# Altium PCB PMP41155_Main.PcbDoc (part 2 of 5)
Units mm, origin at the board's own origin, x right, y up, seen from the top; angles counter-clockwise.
Board outline 74 x 146.5 mm, 8 copper layers (Top Layer, Signal Layer 1, Signal Layer 2, Signal Layer 3, Signal Layer 4, Signal Layer 5, Signal Layer 6, Bottom Layer), stack 1.534 mm thick; 249 components, 190 nets, 902 pads, 747 vias.
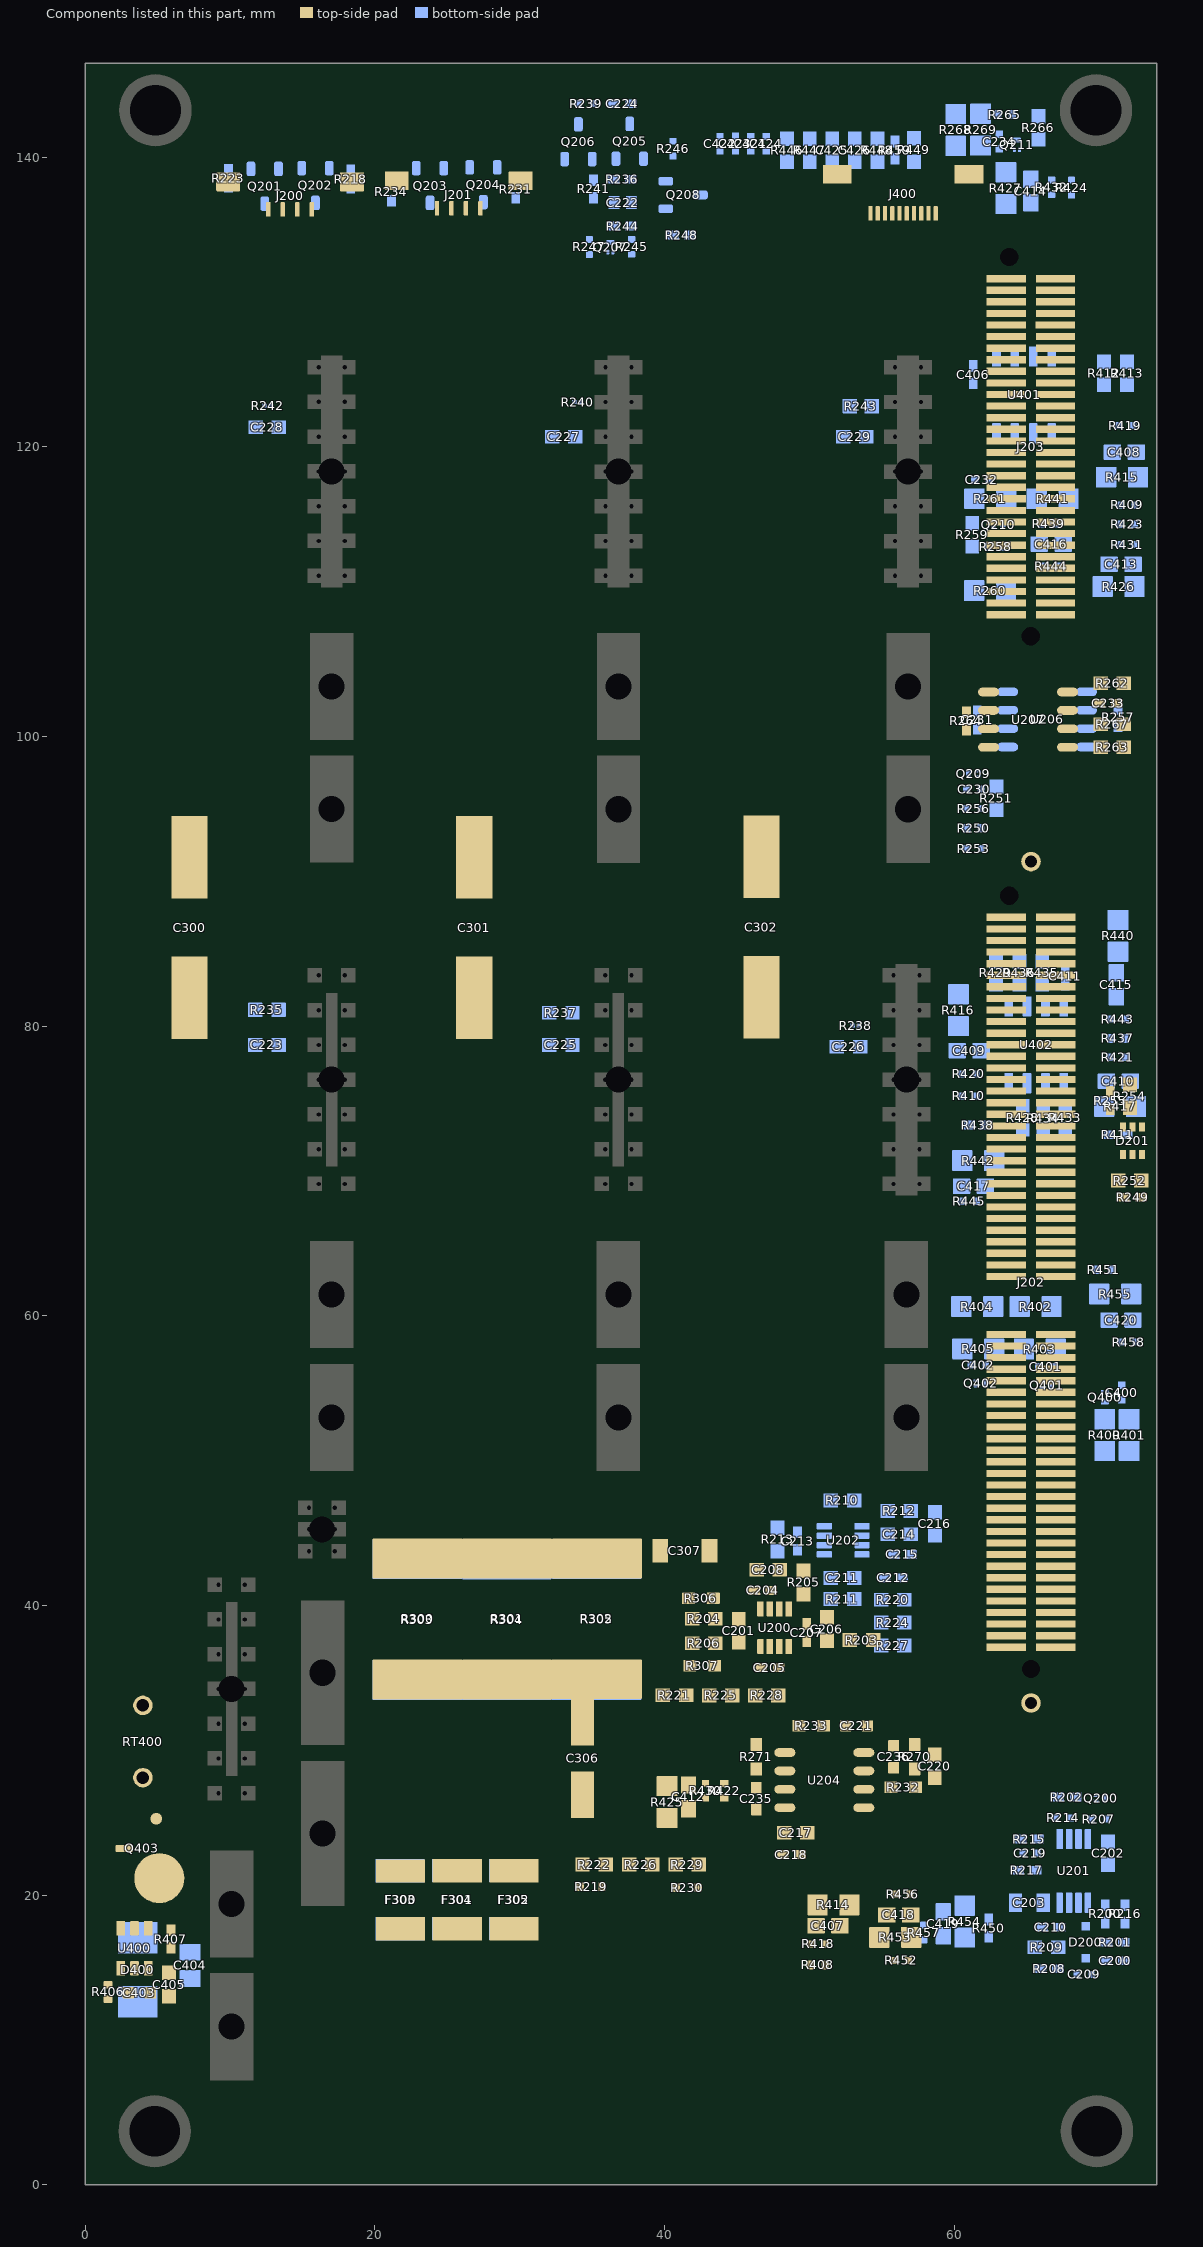
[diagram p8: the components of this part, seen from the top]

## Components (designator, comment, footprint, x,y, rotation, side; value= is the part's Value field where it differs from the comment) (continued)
C230 "885012205001" WCAP-CSGP_0402_L1W0.5H0.5 61.38,96.38 r180 bottom
C231 "CMP-0006623-2" 0402 61.59,101.155 r270 bottom value=0.1uF
C232 "885012205001" WCAP-CSGP_0402_L1W0.5H0.5 61.92,117.74 r0 bottom
C233 "CMP-0006623-2" 0402 70.63,102.3 r0 top value=0.1uF
C234 "885012205001" WCAP-CSGP_0402_L1W0.5H0.5 63.121,141.09 r90 bottom
C235 "06035C100KAT2A" FP-06035C100KAT2A_0603-MFG 46.34,26.664 r90 top value=10pF
C236 "06035C100KAT2A" FP-06035C100KAT2A_0603-MFG 55.825,29.559 r270 top value=10pF
C300 "EMVY630ATR101MKE0S" CAPSMT_62_KE0 7.21,86.81 r90 top value=100uF
C301 "EMVY630ATR101MKE0S" CAPSMT_62_KE0 26.86,86.81 r90 top value=100uF
C302 "EMVY630ATR101MKE0S" CAPSMT_62_KE0 46.7,86.84 r90 top value=100uF
C306 "63PFV22M6.3X8" SM_RADIAL_D 34.35,29.44 r270 top value=22uF
C307 "GRJ31CC72A475KE01L" 1206_180 41.41,43.78 r0 top value=4.7uF
C400 "885012205001" WCAP-CSGP_0402_L1W0.5H0.5 71.574,54.705 r270 bottom
C401 "885012205001" WCAP-CSGP_0402_L1W0.5H0.5 66.33,56.505 r0 bottom
C402 "885012205001" WCAP-CSGP_0402_L1W0.5H0.5 61.67,56.609 r0 bottom
C403 "885012206120" FP-885012206120_0603-MFG 3.74,13.26 r180 top value=100nF
C404 "KAF21KR72A105KU" 0805_150 7.24,15.15 r270 bottom value=1uF
C405 "GRM188R71E104KA01D" 0603 5.796,13.831 r270 top value=0.1uF
C406 "CMP-0006623-2" 0402 61.328,124.99 r270 bottom value=0.1uF
C407 "C0603C153K5RACTU" FP-C0603C153K5RACTU_0603-IPC_A 51.291,17.886 r0 top
C408 "C0603C153K5RACTU" FP-C0603C153K5RACTU_0603-IPC_A 71.75,119.64 r180 bottom
C409 "C0603C153K5RACTU" FP-C0603C153K5RACTU_0603-IPC_A 61.04,78.31 r0 bottom
C410 "C0603C153K5RACTU" FP-C0603C153K5RACTU_0603-IPC_A 71.341,76.208 r0 bottom
C411 "CMP-0006623-2" 0402 67.681,83.465 r270 bottom value=0.1uF
C412 "C0603C153K5RACTU" FP-C0603C153K5RACTU_0603-IPC_A 41.658,26.782 r270 top
C413 "C0603C153K5RACTU" FP-C0603C153K5RACTU_0603-IPC_A 71.53,111.897 r180 bottom
C414 "C0603C153K5RACTU" FP-C0603C153K5RACTU_0603-IPC_A 65.3,137.674 r90 bottom
C415 "C0603C153K5RACTU" FP-C0603C153K5RACTU_0603-IPC_A 71.205,82.865 r270 bottom
C416 "C0603C153K5RACTU" FP-C0603C153K5RACTU_0603-IPC_A 66.71,113.29 r180 bottom
C417 "C0603C153K5RACTU" FP-C0603C153K5RACTU_0603-IPC_A 61.34,68.95 r0 bottom
C418 "C0603C153K5RACTU" FP-C0603C153K5RACTU_0603-IPC_A 56.176,18.636 r180 top
C419 "C0603C153K5RACTU" FP-C0603C153K5RACTU_0603-IPC_A 59.26,18.02 r90 bottom
C420 "C0603C153K5RACTU" FP-C0603C153K5RACTU_0603-IPC_A 71.524,59.71 r0 bottom
C421 "885012205001" WCAP-CSGP_0402_L1W0.5H0.5 45.96,140.93 r270 bottom
C422 "885012205001" WCAP-CSGP_0402_L1W0.5H0.5 43.84,140.93 r270 bottom
C423 "885012205001" WCAP-CSGP_0402_L1W0.5H0.5 44.9,140.95 r270 bottom
C424 "885012205001" WCAP-CSGP_0402_L1W0.5H0.5 47.02,140.93 r270 bottom
C425 "C0603X221K5RACTU" 0603 51.585,140.49 r270 bottom value=220pF
C426 "C0603X221K5RACTU" 0603 53.145,140.49 r270 bottom value=220pF
D200 "BAS316,115" SOD-323 69.084,16.752 r90 bottom value=100V
D201 "BAV99S,115" SOT-363 72.32,72.09 r270 top value=100V
D400 "B180B-13-F" SMB 3.63,14.85 r270 bottom value=80V
F300 "MINIASMDC050F-2" 1812 21.78,19.677 r90 top
F301 "MINIASMDC050F-2" 1812 25.69,19.687 r90 top
F302 "MINIASMDC050F-2" 1812 29.61,19.687 r90 top
F303 "MINIASMDC050F-2" 1812 21.74,19.687 r90 bottom
F304 "MINIASMDC050F-2" 1812 25.65,19.697 r90 bottom
F305 "MINIASMDC050F-2" 1812 29.57,19.697 r90 bottom
J200 "686104183522" Wurth_686104183522 14.147,138.306 r180 top
J201 "686104183522" Wurth_686104183522 25.788,138.377 r180 top
J202 "HSEC8-160-01-L-DV-A-BL" controlCARD-120HSEC 65.332,60.477 r90 top
J203 "HSEC8-130-01-L-DV-A" controlCARD-180HSEC-60pinAddon 65.3,120.02 r90 top
J400 "5051101092" Molex_5051101092 56.48,136.13 r180 top
Q200 "2N7002KL3A-TP" FP-2N7002KL3A-TP_DFN3-MFG 70.11,26.69 r0 bottom
Q201 "BCX71K" SOT-23 12.397,138.001 r270 bottom value="45 V"
Q202 "BCX71K" SOT-23 15.9,138.055 r270 bottom value="45 V"
Q203 "BCX71K" SOT-23 23.813,138.053 r270 bottom value="45 V"
Q204 "BCX71K" SOT-23 27.498,138.108 r270 bottom value="45 V"
Q205 "MMBT4403" SOT-23 37.602,141.102 r90 bottom value="40 V"
Q206 "MMUN2214LT1G" SOT-23 34.057,141.077 r90 bottom value="50 V"
Q207 "2N7002KL3A-TP" FP-2N7002KL3A-TP_DFN3-MFG 36.262,133.797 r90 bottom
Q208 "MMUN2214LT1G" SOT-23 41.29,137.4 r0 bottom value="50 V"
Q209 "2N7002KL3A-TP" FP-2N7002KL3A-TP_DFN3-MFG 61.33,97.44 r180 bottom
Q210 "2N7002KL3A-TP" FP-2N7002KL3A-TP_DFN3-MFG 63.04,114.625 r0 bottom
Q211 "2N7002KL3A-TP" FP-2N7002KL3A-TP_DFN3-MFG 64.335,140.865 r90 bottom
Q400 "2N7002KL3A-TP" FP-2N7002KL3A-TP_DFN3-MFG 70.405,54.38 r270 bottom
Q401 "2N7002KL3A-TP" FP-2N7002KL3A-TP_DFN3-MFG 66.41,55.205 r0 bottom
Q402 "2N7002KL3A-TP" FP-2N7002KL3A-TP_DFN3-MFG 61.84,55.347 r0 bottom
Q403 "IQD016N08NM5CGATMA1" FP-IQD016N08NM5CGATMA1_TTFN-9-MFG 4.91,22.48 r90 top
R200 "CRCW04025K49FKED" 0402 70.444,18.712 r270 bottom value=5.49k
R201 "CRCW040215K0FKED" 0402 71.124,16.752 r0 bottom value=15.0k
R202 "MCR01MZPF10R0" 0402 67.794,26.775 r180 bottom value=10.0
R203 "RC0603JR-070RL" 0603 53.61,37.615 r180 top value=0
R204 "RC0603FR-07100RL" 0603 42.71,39.09 r180 top value=100
R205 "RC0603JR-070RL" 0603 49.605,41.593 r90 top value=0
R206 "RC0603FR-07100RL" 0603 42.71,37.39 r180 top value=100
R207 "ERJ-U02F1002X" FP-ERJ-U02F1002X_0402-MFG 69.994,25.255 r180 bottom value=10k
R208 "CRCW04023K01FKED" 0402 66.574,14.925 r0 bottom value=3.01k
R209 "RC0603FR-07510KL" 0603 66.384,16.405 r0 bottom value=510k
R210 "RC0603JR-070RL" 0603 52.288,47.253 r0 bottom value=0
R211 "RC0603FR-07100RL" 0603 52.288,40.45 r180 bottom value=100
R212 "RC0603JR-070RL" 0603 56.205,46.528 r0 bottom value=0
R213 "RC0603FR-07100RL" 0603 47.81,44.56 r90 bottom value=100
R214 "ERJ-U02F1002X" FP-ERJ-U02F1002X_0402-MFG 67.534,25.335 r180 bottom value=10k
R215 "CRCW04023K57FKED" 0402 65.204,23.875 r180 bottom value=3.57k
R216 "CRCW04023K01FKED" 0402 71.804,18.712 r270 bottom value=3.01k
R217 "ERJ-2RKF1501X" 0402 65.024,21.715 r180 bottom value=1.50k
R218 "CRCW0402330RJNED" 0402 18.346,138.501 r90 bottom value=330
R219 "RK73H1JTTD1000F" FP-RK73H1JTTD1000F_0603-MFG 34.93,20.585 r180 top
R220 "CRCW060328K7FKEA" 0603 55.77,40.395 r180 bottom value=28.7k
R221 "RC0603FR-0728K7L" 0603 40.69,33.797 r180 top value=28.7k
R222 "CRCW060328K7FKEA" 0603 35.14,22.11 r180 top value=28.7k
R223 "CRCW0402330RJNED" 0402 9.891,138.555 r90 bottom value=330
R224 "CRCW060328K7FKEA" 0603 55.758,38.82 r0 bottom value=28.7k
R225 "CRCW060328K7FKEA" 0603 43.88,33.79 r180 top value=28.7k
R226 "RC0603FR-0728K7L" 0603 38.37,22.11 r180 top value=28.7k
R227 "CRCW06033K01FKEA" 0603 55.758,37.235 r180 bottom value=3.01k
R228 "RT0603BRD073K01L" 0603 47.06,33.79 r180 top value=3.01k
R229 "RT0603BRD073K01L" 0603 41.578,22.111 r180 top value=3.01k
R230 "RK73H1JTTD1000F" FP-RK73H1JTTD1000F_0603-MFG 41.578,20.511 r0 top
R231 "CRCW0402330RJNED" 0402 29.738,137.798 r90 bottom value=330
R232 "RC0603JR-130RP" FP-RC0603JR-130RP_0603-MFG 56.486,27.444 r180 top value=0
R233 "RC0603JR-130RP" FP-RC0603JR-130RP_0603-MFG 50.14,31.694 r180 top value=0
R234 "CRCW0402330RJNED" 0402 21.148,137.608 r90 bottom value=330
R235 "CR0603-10W-000T" FP-CR0603-10W-000T_0603-MFG 12.55,81.13 r180 bottom value=0Ω
R236 "CRCW04022K10FKED" 0402 37.085,138.477 r180 bottom value=2.10k
R237 "RC0603JR-070RL" 0603 32.85,80.94 r180 bottom value=0
R238 "CR0201PM0RS001" FP-CR0201PM0RS001_0201-MFG 53.213,80.041 r0 bottom value=0
R239 "ERJ-U02F1002X" FP-ERJ-U02F1002X_0402-MFG 34.587,143.707 r0 bottom value=10k
R240 "CR0201PM0RS001" FP-CR0201PM0RS001_0201-MFG 34.013,123.103 r0 bottom value=0
R241 "CRCW04022K10FKED" 0402 35.1,137.812 r270 bottom value=2.10k
R242 "CR0201PM0RS001" FP-CR0201PM0RS001_0201-MFG 12.6,122.856 r0 bottom value=0
R243 "WSL060300000ZEA9" FP-WSL060300000ZEA9_0603-MFG 53.56,122.82 r180 bottom value=0
R244 "CRCW04024K32FKED" 0402 37.117,135.257 r0 bottom value=4.32k
R245 "ERJ-U02F1002X" FP-ERJ-U02F1002X_0402-MFG 37.732,133.817 r270 bottom value=10k
R246 "ERJ-U02F1002X" FP-ERJ-U02F1002X_0402-MFG 40.59,140.597 r90 bottom value=10k
R247 "ERJ-U02F1002X" FP-ERJ-U02F1002X_0402-MFG 34.817,133.807 r270 bottom value=10k
R248 "CRCW04022K10FKED" 0402 41.19,134.63 r180 bottom value=2.10k
R249 "CRCW04023K30JNED" 0402 72.32,68.19 r0 top value=3.3k
R250 "RC0402JR-07100KL" FP-RC0402JR-07100KL_0402-MFG 61.365,93.665 r0 bottom value=100k
R251 "RC0603FR-074K75L" 0603 62.926,95.755 r270 bottom value=4.75k
R252 "RC0603FR-074K75L" 0603 72.13,69.34 r180 top value=4.75k
R253 "ERJ-H2G0R00X" FP-ERJ-H2G0R00X_0402-MFG 61.36,92.27 r180 bottom value=0
R254 "RC0603FR-074K75L" 0603 72.14,75.16 r90 top value=4.75k
R255 "CRCW04023K30JNED" 0402 70.791,74.868 r270 top value=3.3k
R256 "ERJ-H2G0R00X" FP-ERJ-H2G0R00X_0402-MFG 61.34,95.03 r180 bottom value=0
R257 "CRCW0402120RJNED" 0402 71.317,101.332 r270 bottom value=120
R258 "RC0402JR-07100KL" FP-RC0402JR-07100KL_0402-MFG 62.89,113.12 r180 bottom value=100k
R259 "RC0603FR-074K75L" 0603 61.259,113.926 r270 bottom value=4.75k
R260 "JR0805X35E" FP-JR0805X35E_0805-MFG 62.49,110.08 r180 bottom value=0
R261 "JR0805X35E" FP-JR0805X35E_0805-MFG 62.5,116.42 r0 bottom value=0
R262 "RC0603FR-074K75L" 0603 70.91,103.69 r180 top value=4.75k
R263 "RC0603FR-074K75L" 0603 70.922,99.257 r0 top value=4.75k
R264 "CRCW0402120RJNED" 0402 60.85,101.09 r90 top value=120
R265 "RC0402JR-07100KL" FP-RC0402JR-07100KL_0402-MFG 63.51,142.95 r0 bottom value=100k
R266 "RC0603FR-074K75L" 0603 65.82,142.04 r90 bottom value=4.75k
R267 "RC0603FR-0710K7L" 0603 70.922,100.857 r180 top value=10.7k
R268 "JR0805X35E" FP-JR0805X35E_0805-MFG 60.11,141.89 r270 bottom value=0
R269 "JR0805X35E" FP-JR0805X35E_0805-MFG 61.83,141.91 r90 bottom value=0
R270 "RC0603JR-130RP" FP-RC0603JR-130RP_0603-MFG 57.27,29.559 r90 top value=0
R271 "RC0603JR-130RP" FP-RC0603JR-130RP_0603-MFG 46.34,29.559 r90 top value=0
R300 "PU3921FKNP90U4L" FP-PU3921FKNP90U4L_3921-MFG 22.948,39.072 r270 top value=400µ
R301 "PU3921FKNP90U4L" FP-PU3921FKNP90U4L_3921-MFG 29.138,39.072 r270 top value=400µ
R302 "PU3921FKNP90U4L" FP-PU3921FKNP90U4L_3921-MFG 35.338,39.082 r270 top value=400µ
R303 "PU3921FKNP90U4L" FP-PU3921FKNP90U4L_3921-MFG 22.928,39.032 r270 bottom value=400µ
R304 "PU3921FKNP90U4L" FP-PU3921FKNP90U4L_3921-MFG 29.108,39.012 r270 bottom value=400µ
R305 "PU3921FKNP90U4L" FP-PU3921FKNP90U4L_3921-MFG 35.308,39.042 r270 bottom value=400µ
R306 "RC0603JR-130RP" FP-RC0603JR-130RP_0603-MFG 42.52,40.493 r180 top value=0
R307 "RC0603JR-130RP" FP-RC0603JR-130RP_0603-MFG 42.61,35.85 r180 top value=0
R400 "JR0805X35E" FP-JR0805X35E_0805-MFG 70.405,51.765 r270 bottom value=0
R401 "JR0805X35E" FP-JR0805X35E_0805-MFG 72.087,51.765 r90 bottom value=0
R402 "JR0805X35E" FP-JR0805X35E_0805-MFG 65.63,60.64 r180 bottom value=0
R403 "JR0805X35E" FP-JR0805X35E_0805-MFG 65.92,57.71 r0 bottom value=0
R404 "JR0805X35E" FP-JR0805X35E_0805-MFG 61.6,60.64 r180 bottom value=0
R405 "JR0805X35E" FP-JR0805X35E_0805-MFG 61.67,57.72 r0 bottom value=0
R406 "RMCF0402FT100R" FP-RMCF0402FT100R_0402-MFG 1.58,13.32 r90 top value=100
R407 "MCR01MZPF1001" 0402 5.92,16.97 r270 top value=1.00k
R408 "RC0402JR-07100KL" FP-RC0402JR-07100KL_0402-MFG 50.601,15.181 r0 top value=100k
R409 "ERJ-U02F1002X" FP-ERJ-U02F1002X_0402-MFG 71.94,116 r180 bottom value=10k
R410 "ERJ-U02F1002X" FP-ERJ-U02F1002X_0402-MFG 61.02,75.19 r0 bottom value=10k
R411 "ERJ-2GEJ203X" 0402 71.316,72.503 r0 bottom value=20k
R412 "RC0603FR-074K75L" 0603 70.35,125.1 r90 bottom value=4.75k
R413 "RC0603FR-074K75L" 0603 71.94,125.1 r90 bottom value=4.75k
R414 "JR0805X35E" FP-JR0805X35E_0805-MFG 51.671,19.326 r180 top value=0
R415 "JR0805X35E" FP-JR0805X35E_0805-MFG 71.6,117.91 r0 bottom value=0
R416 "JR0805X35E" FP-JR0805X35E_0805-MFG 60.3,81.11 r270 bottom value=0
R417 "JR0805X35E" FP-JR0805X35E_0805-MFG 71.46,74.46 r0 bottom value=0
R418 "ERJ-U02F1002X" FP-ERJ-U02F1002X_0402-MFG 50.611,16.631 r180 top value=10k
R419 "ERJ-U02F1002X" FP-ERJ-U02F1002X_0402-MFG 71.83,121.48 r0 bottom value=10k
R420 "ERJ-U02F1002X" FP-ERJ-U02F1002X_0402-MFG 61.01,76.71 r180 bottom value=10k
R421 "ERJ-U02F1002X" FP-ERJ-U02F1002X_0402-MFG 71.298,77.859 r180 bottom value=10k
R422 "RC0402JR-07100KL" FP-RC0402JR-07100KL_0402-MFG 44.139,27.208 r270 top value=100k
R423 "ERJ-U02F1002X" FP-ERJ-U02F1002X_0402-MFG 71.94,114.658 r180 bottom value=10k
R424 "ERJ-U02F1002X" FP-ERJ-U02F1002X_0402-MFG 68.11,137.91 r90 bottom value=10k
R425 "JR0805X35E" FP-JR0805X35E_0805-MFG 40.178,26.432 r90 top value=0
R426 "JR0805X35E" FP-JR0805X35E_0805-MFG 71.355,110.362 r0 bottom value=0
R427 "JR0805X35E" FP-JR0805X35E_0805-MFG 63.575,137.87 r270 bottom value=0
R428 "RC0603FR-074K75L" 0603 64.74,73.67 r270 bottom value=4.75k
R429 "RC0603FR-074K75L" 0603 62.885,83.695 r90 bottom value=4.75k
R430 "ERJ-U02F1002X" FP-ERJ-U02F1002X_0402-MFG 42.841,27.212 r90 top value=10k
R431 "ERJ-U02F1002X" FP-ERJ-U02F1002X_0402-MFG 71.94,113.26 r0 bottom value=10k
R432 "ERJ-U02F1002X" FP-ERJ-U02F1002X_0402-MFG 66.736,137.927 r270 bottom value=10k
R433 "RC0603FR-074K75L" 0603 67.68,73.67 r270 bottom value=4.75k
R434 "RC0603FR-074K75L" 0603 66.16,73.648 r270 bottom value=4.75k
R435 "RC0603FR-074K75L" 0603 66.082,83.695 r90 bottom value=4.75k
R436 "RC0603FR-074K75L" 0603 64.508,83.695 r90 bottom value=4.75k
R437 "RC0402JR-07100KL" FP-RC0402JR-07100KL_0402-MFG 71.29,79.16 r180 bottom value=100k
R438 "ERJ-2GEJ203X" 0402 61.637,73.18 r0 bottom value=20k
R439 "ERJ-U02F1002X" FP-ERJ-U02F1002X_0402-MFG 66.52,114.706 r180 bottom value=10k
R440 "JR0805X35E" FP-JR0805X35E_0805-MFG 71.32,86.24 r270 bottom value=0
R441 "JR0805X35E" FP-JR0805X35E_0805-MFG 66.8,116.42 r0 bottom value=0
R442 "JR0805X35E" FP-JR0805X35E_0805-MFG 61.667,70.72 r180 bottom value=0
R443 "ERJ-U02F1002X" FP-ERJ-U02F1002X_0402-MFG 71.316,80.499 r0 bottom value=10k
R444 "ERJ-U02F1002X" FP-ERJ-U02F1002X_0402-MFG 66.71,111.777 r0 bottom value=10k
R445 "ERJ-U02F1002X" FP-ERJ-U02F1002X_0402-MFG 61.03,67.91 r180 bottom value=10k
R446 "RC0603FR-074K75L" 0603 48.465,140.48 r90 bottom value=4.75k
R447 "RC0603FR-074K75L" 0603 50.025,140.48 r90 bottom value=4.75k
R448 "RC0603FR-074K75L" 0603 54.705,140.49 r90 bottom value=4.75k
R449 "RC0603FR-074K75L" 0603 57.23,140.51 r90 bottom value=4.75k
R450 "ERJ-2GEJ203X" 0402 62.381,17.72 r90 bottom value=20k
R451 "RC0402JR-07100KL" FP-RC0402JR-07100KL_0402-MFG 70.33,63.185 r0 bottom value=100k
R452 "ERJ-U02F1002X" FP-ERJ-U02F1002X_0402-MFG 56.336,15.491 r180 top value=10k
R453 "JR0805X35E" FP-JR0805X35E_0805-MFG 55.936,17.086 r0 top value=0
R454 "JR0805X35E" FP-JR0805X35E_0805-MFG 60.731,18.178 r270 bottom value=0
R455 "JR0805X35E" FP-JR0805X35E_0805-MFG 71.13,61.51 r180 bottom value=0
R456 "ERJ-U02F1002X" FP-ERJ-U02F1002X_0402-MFG 56.443,20.08 r0 top value=10k
R457 "ERJ-U02F1002X" FP-ERJ-U02F1002X_0402-MFG 57.901,17.42 r270 bottom value=10k
R458 "ERJ-U02F1002X" FP-ERJ-U02F1002X_0402-MFG 72.048,58.19 r180 bottom value=10k
R459 "MCR01MZPF10R0" 0402 55.918,140.49 r270 bottom value=10.0
RT400 "B59751B0120A070" TDK_B751 3.98,30.61 r0 top value=50
U200 "INA296A4IDDF" DDF0008A-MFG 47.603,38.468 r90 top
U201 "TLV2197-Q1" DGK0008A-MFG 68.264,21.675 r90 bottom
U202 "INA296A3IDDF" DDF0008A-MFG 52.338,44.503 r0 bottom
U204 "TLV9062IDR" D0008A_N 51.04,27.944 r180 top
U206 "SN65HVD234D" D0008A_N 66.42,101.185 r0 bottom
U207 "SN65HVD75DR" D0008A_N 65.105,101.172 r180 top
U400 "LM5050MK-1/NOPB" DDC0006A_N 3.405,16.335 r90 top
U401 "M24M01-RMN6TP" FP-M24M01-RMN6TP_SOIC8-MFG 64.831,123.59 r90 bottom
U402 "M24M01-RMN6TP" FP-M24M01-RMN6TP_SOIC8-MFG 65.67,78.72 r270 bottom

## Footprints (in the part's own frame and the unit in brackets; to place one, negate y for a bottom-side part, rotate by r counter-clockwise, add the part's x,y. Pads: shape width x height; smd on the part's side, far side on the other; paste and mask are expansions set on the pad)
0402 [mm] "0402 from SM-752 data"
  rect 0.8x0.6 smd: 1(-0.6,0) 2(0.6,0)
  silkscreen extent -1.22,-0.52 1.22,0.52, body extent -0.55,-0.3 0.55,0.3, height 0.6
0603 [mm] "0603 from SM-752 data"
  rect 1x0.95 smd: 1(-0.8,0) 2(0.8,0)
  silkscreen extent -1.52,-0.69 1.52,0.69, body extent -0.87,-0.47 0.87,0.47, height 1
0805_150 [mm] "0805 / 1.5 mm height"
  rect 1.15x1.45 smd: 1(-0.9,0) 2(0.9,0)
  silkscreen extent -0.1,-0.8 0.1,0.8, body extent -1.1,-0.72 1.1,0.72, height 1.5
1206_180 [mm] "1206_180"
  rect 1.1x1.6 smd: 1(-1.7,0) 2(1.7,0)
  silkscreen extent -0.9,-1 0.9,1, body extent -1.75,-0.95 1.75,0.95, height 1.8
1812 [mm]
  rect 1.6x3.4 smd: 1(-2,0) 2(2,0)
  silkscreen extent -0.8,-1.6 0.8,1.6, body extent -2.4,-1.7 2.4,1.7, height 1.35
CAPSMT_62_KE0 [mm] "12.5 x 13.5mm:  Chemi-Con KE0"
  rect 5.7x2.5 smd: 1(-4.85,0) 2(4.85,0)
  silkscreen extent -6.6,-6.6 6.6,6.6, body extent -6.6,-6.6 6.6,6.6, height 14
controlCARD-120HSEC [mm] "Pads are not numbered according to Samtec datasheet."
  rect 0.5x2.724 smd: 1(-23.357,-1.678) 2(-23.357,1.722) 3(-22.557,-1.678) 4(-22.557,1.722) 5(-21.757,-1.678) 6(-21.757,1.722) 7(-20.957,-1.678) 8(-20.957,1.722) 9(-20.157,-1.678) 10(-20.157,1.722) 11(-19.357,-1.678) 12(-19.357,1.722) 13(-18.557,-1.678) 14(-18.557,1.722) 15(-17.757,-1.678) 16(-17.757,1.722) 17(-16.957,-1.678) 18(-16.957,1.722) 19(-16.157,-1.678) 20(-16.157,1.722) 21(-15.357,-1.678) 22(-15.357,1.722) 23(-14.557,-1.678) 24(-14.557,1.722) 25(-13.757,-1.678) 26(-13.757,1.722) 27(-12.957,-1.678) 28(-12.957,1.722) 29(-12.157,-1.678) 30(-12.157,1.722) 31(-11.357,-1.678) 32(-11.357,1.722) 33(-10.557,-1.678) 34(-10.557,1.722) 35(-9.757,-1.678) 36(-9.757,1.722) 37(-8.957,-1.678) 38(-8.957,1.722) 39(-8.157,-1.678) 40(-8.157,1.722) 41(-7.357,-1.678) 42(-7.357,1.722) 43(-6.557,-1.678) 44(-6.557,1.722) 45(-5.757,-1.678) 46(-5.757,1.722) 47(-4.957,-1.678) 48(-4.957,1.722) 49(-4.157,-1.678) 50(-4.157,1.722) 51(-3.357,-1.678) 52(-3.357,1.722) 53(-2.557,-1.678) 54(-2.557,1.722) 55(-1.757,-1.678) 56(-1.757,1.722) 57(2.243,-1.678) 58(2.243,1.722) 59(3.043,-1.678) 60(3.043,1.722) 61(3.843,-1.678) 62(3.843,1.722) 63(4.643,-1.678) 64(4.643,1.722) 65(5.443,-1.678) 66(5.443,1.722) 67(6.243,-1.678) 68(6.243,1.722) 69(7.043,-1.678) 70(7.043,1.722) 71(7.843,-1.678) 72(7.843,1.722) 73(8.643,-1.678) 74(8.643,1.722) 75(9.443,-1.678) 76(9.443,1.722) 77(10.243,-1.678) 78(10.243,1.722) 79(11.043,-1.678) 80(11.043,1.722) 81(11.843,-1.678) 82(11.843,1.722) 83(12.643,-1.678) 84(12.643,1.722) 85(13.443,-1.678) 86(13.443,1.722) 87(14.243,-1.678) 88(14.243,1.722) 89(15.043,-1.678) 90(15.043,1.722) 91(15.843,-1.678) 92(15.843,1.722) 93(16.643,-1.678) 94(16.643,1.722) 95(17.443,-1.678) 96(17.443,1.722) 97(18.243,-1.678) 98(18.243,1.722) 99(19.043,-1.678) 100(19.043,1.722) 101(19.843,-1.678) 102(19.843,1.722) 103(20.643,-1.678) 104(20.643,1.722) 105(21.443,-1.678) 106(21.443,1.722) 107(22.243,-1.678) 108(22.243,1.722) 109(23.043,-1.678) 110(23.043,1.722) 111(23.843,-1.678) 112(23.843,1.722) 113(24.643,-1.678) 114(24.643,1.722) 115(25.443,-1.678) 116(25.443,1.722) 117(26.243,-1.678) 118(26.243,1.722) 119(27.043,-1.678) 120(27.043,1.722)
  round 0.025 hole 1.27 unplated mask+0.876: 181(-24.857,0.022) 182(28.543,1.522)
  round 1.348 hole 0.84: 185(-27.207,0.022) 186(30.893,0.022)
  silkscreen extent -32.11,-3.86 35.8,3.9, body extent -31.75,-3.48 35.3,3.52, height 12.35
controlCARD-180HSEC-60pinAddon [mm] "Pads are not numbered according to datasheet."
  round 0.025 hole 1.27 unplated mask+0.876: 61(-13.1,0) 62(13.1,1.5)
  rect 0.5x2.724 smd: 121(-11.6,-1.7) 122(-11.6,1.7) 123(-10.8,-1.7) 124(-10.8,1.7) 125(-10,-1.7) 126(-10,1.7) 127(-9.2,-1.7) 128(-9.2,1.7) 129(-8.4,-1.7) 130(-8.4,1.7) 131(-7.6,-1.7) 132(-7.6,1.7) 133(-6.8,-1.7) 134(-6.8,1.7) 135(-6,-1.7) 136(-6,1.7) 137(-5.2,-1.7) 138(-5.2,1.7) 139(-4.4,-1.7) 140(-4.4,1.7) 141(-3.6,-1.7) 142(-3.6,1.7) 143(-2.8,-1.7) 144(-2.8,1.7) 145(-2,-1.7) 146(-2,1.7) 147(-1.2,-1.7) 148(-1.2,1.7) 149(-0.4,-1.7) 150(-0.4,1.7) 151(0.4,-1.7) 152(0.4,1.7) 153(1.2,-1.7) 154(1.2,1.7) 155(2,-1.7) 156(2,1.7) 157(2.8,-1.7) 158(2.8,1.7) 159(3.6,-1.7) 160(3.6,1.7) 161(4.4,-1.7) 162(4.4,1.7) 163(5.2,-1.7) 164(5.2,1.7) 165(6,-1.7) 166(6,1.7) 167(6.8,-1.7) 168(6.8,1.7) 169(7.6,-1.7) 170(7.6,1.7) 171(8.4,-1.68) 172(8.4,1.7) 173(9.2,-1.7) 174(9.2,1.7) 175(10,-1.7) 176(10,1.7) 177(10.8,-1.7) 178(10.8,1.7) 179(11.6,-1.7) 180(11.6,1.7)
  silkscreen extent -14.68,-3.88 14.68,3.88, body extent -14.3,-3.5 14.3,3.5, height 7.95
D0008A_N [mm] "SOIC, 8-Leads, Body 4.9x3.9mm, Pitch 1.27mm, IPC Medium Density"
  oval 1.45x0.6 smd: 1(-2.725,1.905) 2(-2.725,0.635) 3(-2.725,-0.635) 4(-2.725,-1.905) 5(2.725,-1.905) 6(2.725,-0.635) 7(2.725,0.635) 8(2.725,1.905)
  silkscreen extent -3.3,-2.5 0.9,2.5, body extent -3,-2.45 3,2.45, height 1.63
DDC0006A_N [mm]
  rrect17% 1x0.6 smd: 1(-1.375,0.95) 2(-1.375,0) 3(-1.375,-0.95) 4(1.375,-0.95) 5(1.375,0) 6(1.375,0.95)
  silkscreen extent -1.75,-1.52 0.7,1.53, body extent -1.43,-1.48 1.43,1.49, height 0.92
DDF0008A-MFG [mm]
  rrect22% 1.05x0.45 smd paste+0 mask+0: 1(-1.3,0.975) 2(-1.3,0.325) 3(-1.3,-0.325) 4(-1.3,-0.975) 5(1.3,-0.975) 6(1.3,-0.325) 7(1.3,0.325) 8(1.3,0.975)
  silkscreen extent -2.01,-1.48 0.4,1.67, body extent -1.41,-1.45 1.41,1.45, height 1.1
DGK0008A-MFG [mm] "Recommended Land Pattern"
  rrect22% 1.4x0.45 smd paste+0 mask+0: 1(-2.2,0.975) 2(-2.2,0.325) 3(-2.2,-0.325) 4(-2.2,-0.975) 5(2.2,-0.975) 6(2.2,-0.325) 7(2.2,0.325) 8(2.2,0.975)
  silkscreen extent -3.57,-1.55 1.1,1.55, body extent -2.45,-1.5 2.45,1.5, height 1.1
FP-2N7002KL3A-TP_DFN3-MFG [mm]
  rrect50% 0.35x0.2 smd paste+0 mask+0: 1(-0.325,0.175) 2(-0.325,-0.175)
  rrect29% 0.35x0.55 smd paste+0 mask+0: 3(0.325,0)
  silkscreen extent -1.17,-0.66 0.53,0.67, body extent -0.5,-0.3 0.5,0.3, height 0.55
FP-06035C100KAT2A_0603-MFG [mm]
  rrect13% 0.8x0.75 smd paste+0 mask+0: 1(-0.75,0) 2(0.75,0)
  silkscreen extent -0.87,-0.77 0.87,0.77, body extent -0.8,-0.41 0.8,0.41, height 0.9
FP-885012206120_0603-MFG [mm]
  rrect13% 0.8x0.8 smd paste+0 mask+0: 1(-0.75,0) 2(0.75,0)
  silkscreen extent -0.85,-0.77 0.85,0.77, body extent -0.8,-0.4 0.8,0.4, height 0.87
FP-C0603C153K5RACTU_0603-IPC_A [mil]
  rrect9% 47.5x41.66 smd paste+0 mask+0: 1(-32.51,0) 2(32.51,0)
  body extent -31,-16 31,16, height 34
FP-C0603C474K4RAC7867_0603-MFG [mm]
  rrect13% 0.75x0.9 smd paste+0 mask+0: 1(-0.6,0) 2(0.6,0)
  silkscreen extent -0.8,-0.9 0.8,0.9, body extent -0.8,-0.4 0.8,0.4, height 0.87
FP-CR0201PM0RS001_0201-MFG [mm] "Recommended Land Pattern"
  rrect36% 0.35x0.275 smd paste+0 mask+0: 1(-0.225,0) 2(0.225,0)
  silkscreen extent -0.32,-0.52 0.32,0.52, body extent -0.3,-0.15 0.3,0.15, height 0.26
FP-CR0603-10W-000T_0603-MFG [mm]
  rrect10% 1x1 smd paste+0 mask+0: 1(-0.8,0) 2(0.8,0)
  silkscreen extent -0.85,-0.9 0.85,0.9, body extent -0.8,-0.4 0.8,0.4, height 0.55
FP-ERJ-H2G0R00X_0402-MFG [mm]
  rrect21% 0.475x0.5 smd paste+0 mask+0: 1(-0.512,0) 2(0.513,0)
  silkscreen extent -0.53,-0.69 0.53,0.72, body extent -0.5,-0.25 0.5,0.25, height 0.4
FP-ERJ-U02F1002X_0402-MFG [mm]
  rrect21% 0.475x0.5 smd paste+0 mask+0: 1(-0.512,0) 2(0.513,0)
  silkscreen extent -0.53,-0.63 0.53,0.63, body extent -0.5,-0.25 0.5,0.25, height 0.4
FP-IQD016N08NM5CGATMA1_TTFN-9-MFG [mm]
  round 3.455 smd paste-1000 mask-1000: 1-2-3-4(-1.302,-0.207)
  round 0.81 smd paste-1000 mask-1000: 5-6-7-8(2.8,0)
  rrect20% 0.5x1.2 smd paste-1000 mask+0: 9(0.75,2.2)
  Top Layer region: 3.25,-2.155 2.35,-2.155 2.35,2.155 3.25,2.155
  Top Layer region: 1.05,-2.155 -3.25,-2.155 -3.25,2.155 0.1,2.155 0.1,1.105 1.05,1.105
  silkscreen extent -3.92,-2.55 3.05,2.55, body extent -3,-2.5 3,2.5, height 1.1
FP-JR0805X35E_0805-MFG [mm]
  rrect7% 1.4x1.44 smd paste+0 mask+0: 1(-1.1,0) 2(1.1,0)
  silkscreen extent 0,-0.72 0,0.72, body extent -1,-0.63 1,0.63, height 0.55
FP-M24M01-RMN6TP_SOIC8-MFG [mm]
  rrect17% 1.4x0.6 smd paste+0 mask+0: 1(-2.65,1.905) 2(-2.65,0.635) 3(-2.65,-0.635) 4(-2.65,-1.905) 5(2.65,-1.905) 6(2.65,-0.635) 7(2.65,0.635) 8(2.65,1.905)
  body extent -2.95,-2.47 3.05,2.43, height 1.7
FP-PU3921FKNP90U4L_3921-MFG [mm]
  rrect4% 2.75x6.2 smd paste+0 mask+0: 1(-4.175,0) 2(4.175,0)
  silkscreen extent -2.42,-2.73 2.42,2.73, body extent -5,-2.6 5,2.6, height 1.81
FP-RC0402JR-07100KL_0402-MFG [mm]
  rrect20% 0.5x0.6 smd paste+0 mask+0: 1(-0.5,0) 2(0.5,0)
  silkscreen extent -0.5,-0.67 0.5,0.67, body extent -0.5,-0.25 0.5,0.25, height 0.4
FP-RC0603JR-130RP_0603-MFG [mm]
  rrect13% 0.9x0.8 smd paste+0 mask+0: 1(-0.85,0) 2(0.85,0)
  silkscreen extent 0,-0.45 0,0.45, body extent -0.8,-0.4 0.8,0.4, height 0.55
FP-RK73H1JTTD1000F_0603-MFG [mm]
  rrect20% 0.5x0.6 smd paste+0 mask+0: 1(-0.75,0) 2(0.75,0)
  silkscreen extent -0.13,-0.45 0.13,0.45, body extent -0.8,-0.4 0.8,0.4, height 0.55
FP-RMCF0402FT100R_0402-MFG [mm]
  rrect20% 0.5x0.6 smd paste+0 mask+0: 1(-0.5,0) 2(0.5,0)
  silkscreen extent -0.55,-0.7 0.55,0.7, body extent -0.5,-0.25 0.5,0.25, height 0.4
FP-WSL060300000ZEA9_0603-MFG [mm]
  rrect10% 1.01x1.01 smd paste+0 mask+0: 1(-0.755,0) 2(0.755,0)
  silkscreen extent -0.89,-0.88 0.89,0.88, body extent -0.76,-0.38 0.76,0.38, height 0.46
Molex_5051101092 [mm] "FPC Connector, 0.5mm, 10 Pos, R/A, SMT"
  rrect33% 0.3x1 smd: 1(-2.25,0) 2(-1.75,0) 3(-1.25,0) 4(-0.75,0) 5(-0.25,0) 6(0.25,0) 7(0.75,0) 8(1.25,0) 9(1.75,0) 10(2.25,0)
  rrect8% 2x1.3 smd: MP1(-4.55,-2.7) MP2(4.55,-2.7)
  body extent -5.25,-5.1 5.25,0.2, height 1.88
SM_RADIAL_D [mm] "6.3 x 5.8mm:  Panasonic D"
  rect 3.2x1.6 smd: 1(-2.5,0) 2(2.5,0)
  silkscreen extent -3.4,-3.4 3.4,3.4, body extent -3.4,-3.4 3.4,3.4, height 6.1
SMB [mm] "Molded Diode, 2-Leads, Body 5.4x3.6mm, IPC Medium Density, based on OnSemi component dimensions"
  rect 2.159x2.743 smd: 1(-2.21,0) 2(2.21,0)
  silkscreen extent -3.94,-2.08 3.18,2.08, body extent -2.7,-1.8 2.7,1.8, height 2.32
SOD-323 [mm] "NXP recommended land pattern"
  rect 0.6x0.6 smd paste-0.05: 1(-1.1,0) 2(1.1,0)
  silkscreen extent -2.06,-0.86 1.53,0.86, body extent -1.3,-0.67 1.3,0.68, height 1.1
SOT-23 [mm] "SOT23, 3-Leads, Body 2.9x1.3mm, Pitch 0.95mm, Lead Span 2.5mm, IPC Medium Density"
  rrect50% 1x0.6 smd: 1(-1.2,0.95) 2(-1.2,-0.95) 3(1.2,0)
  silkscreen extent -1.62,-1.5 0.7,1.5, body extent -1.16,-1.45 1.21,1.45, height 1
SOT-363 [mm]
  rect 0.6x0.42 smd mask+0.051: 1(-0.95,0.65) 2(-0.95,0) 3(-0.95,-0.65) 4(0.95,-0.65) 5(0.95,0) 6(0.95,0.65)
  silkscreen extent -0.38,-1.02 0.38,1.02, body extent -1.1,-1.1 1.1,1.1, height 1.12
TDK_B751 [mm] "TH, 2-Leads, Dia 12.5mm, Pin Spacing 5mm"
  round 1.35 hole 0.85: 1(0,2.5) 2(0,-2.5)
  silkscreen extent -3.5,-6.25 3.5,6.25, body extent -3.48,-6.2 3.48,6.25, height 16.49
WCAP-CSGP_0402_L1W0.5H0.5 [mm] "Ceramic Capacitors, body 1x0.5mm"
  rect 0.5x0.5 smd: 1(-0.5,0) 2(0.5,0)
  body extent -0.5,-0.25 0.5,0.25, height 0.5
WCAP-CSGP_0805_L2W1.25H1.25 [mm] "Ceramic Capacitors, body 2x1.25mm"
  rect 0.9x1.3 smd: 1(-0.95,0) 2(0.95,0)
  body extent -1,-0.63 1,0.63, height 1.25
Wurth_686104183522 [mm] "FPC Connector, 1mm, 4 Pos, R/A, SMT"
  rrect33% 0.3x1 smd: 1(-1.5,1.9) 2(-0.5,1.9) 3(0.5,1.9) 4(1.5,1.9)
  rrect8% 1.65x1.3 smd: MP1(-4.275,0) MP2(4.275,0)
  body extent -5.1,-2.4 5.1,1.85, height 1.25

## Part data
C200: library part CMP-0078218-1, "CAP, CERM, 0.01 µF, 16 V,+/- 10%, X7R, 0402", Cap_Case=0402, Manufacturer=Kemet, Supplier Part Number 1=399-1038-1-ND, TempCo=X7R, Tolerance_%=10%, Value2=16V, ValueDisplayed=0.01µF
C201 C211: "CAP, CERM, 68 pF, 50 V,+/- 5%, C0G/NP0, 0603", Cap_Case=0603, Manufacturer=AVX, Supplier Part Number 1=478-1173-1-ND, TempCo=C0G/NP0, Tolerance_%=5, Value1="0.144 ohm", Value2=50V, ValueDisplayed=68pF
C202: library part CMP-0083626-1, "CAP, CERM, 0.1 µF, 16 V,+/- 10%, X7R, AEC-Q200 Grade 1, 0603", Cap_Case=0603, Manufacturer=AVX, Supplier Part Number 1=478-9382-1-ND, TempCo=X7R, Tolerance_%=10%, Value2=16V, ValueDisplayed=0.1µF
C203: library part CMP-0104520-1, "WCAP-CSGP Multilayer Ceramic Chip Capacitor, General Purpose, size 0805, X5R, 4.7µF, 16VDC", Capacitance Tolerance=+/-20%, Case/Size Code=0805, Insulation Resistance=0.02GOhm, Manufacturer="Wurth Elektronik", Operating Temperature Max=85°C, Operating Temperature Min=-55°C, Rated Voltage (DC)=16V
C204 C205 C212 C213: "CAP, CERM, 47 pF, 50 V,+/- 1%, C0G/NP0, 0402", Cap_Case=0402, Manufacturer=MuRata, Supplier Part Number 1=490-6241-1-ND, TempCo=C0G/NP0, Tolerance_%=1, Value2=50V, ValueDisplayed=47pF
C206 C214: "CAP, CERM, 1 µF, 16 V,+/- 10%, X7R, 0603", Cap_Case=0603, Manufacturer=TDK, Supplier Part Number 1=445-1604-1-ND, TempCo=X7R, Tolerance_%=10, Value1="0.0057 ohm", Value2=16V, ValueDisplayed=1µF
C207 C215: "CAP, CERM, 0.1uF, 6.3V, +/-10%, X7R, 0402", Cap_Case=0402, Manufacturer=MuRata, Supplier Part Number 1=GRM155R70J104KA01D-ND, TempCo=X7R, Tolerance_%=10, Value1=Unknown, Value2=6.3V, ValueDisplayed=0.1uF
C208 C216 C220: "CAP, CERM, 10 pF, 50 V,+/- 1%, C0G/NP0, 0603", Cap_Case=0603, Manufacturer=Kemet, Supplier Part Number 1=399-9958-1-ND, TempCo=C0G/NP0, Tolerance_%=1, Value2=50V, ValueDisplayed=10pF
C209 C219: library part CMP-0115372-1, "WCAP-CSGP Multilayer Ceramic Chip Capacitor, General Purpose, size 0402, X7R, 1nF, 50VDC", Capacitance Tolerance=+/-10%, Case/Size Code=0402, Insulation Resistance=10GOhm, Manufacturer="Wurth Elektronik", Operating Temperature Max=125°C, Operating Temperature Min=-55°C, Rated Voltage (DC)=50V
C210 C218: library part CMP-0006623-2, "CAP, CERM, 0.1 uF, 6.3 V, +/- 10%, X7R, 0402", Cap_Case=0402, Manufacturer=MuRata, Supplier Part Number 1=GRM155R70J104KA01D-ND, TempCo=X7R, Tolerance_%=10%, Value1=Unknown, Value2=6.3V, ValueDisplayed=0.1uF
C217: library part CMP-0079154-1, "CAP, CERM, 1 µF, 16 V,+/- 10%, X7R, AEC-Q200 Grade 1, 0603", Cap_Case=0603, Manufacturer=MuRata, Supplier Part Number 1=490-12657-1-ND, TempCo=X7R, Tolerance_%=10%, Value2=16V, ValueDisplayed=1µF
C221 C235 C236: library part CMP-0046668-1, "10 pF ±10% 50V Ceramic Capacitor X7R 0603 (1608 Metric)", Digikey Part Number=478-11375-1-ND, Manufacturer="KYOCERA AVX", Mouser Part Number=581-06035C100KAT2A, Operating Temperature Range="-55°C to +125°C", TempCo=15%, Temperature Characteristic=X7R, Tolerance_%=10%, ValueDisplayed=10pF
C222: library part CMP-0095164-1, "0.47 µF ±10% 16V Ceramic Capacitor X7R 0603 (1608 Metric)", Digikey Part Number=399-C0603C474K4RAC7867CT-ND, Manufacturer=KEMET, Mouser Part Number=80-C0603C474K4R, Operating Temperature Range="-55°C to +125°C", TempCo=15%, Temperature Characteristic=X7R, Tolerance_%=10%, ValueDisplayed=0.47uF
C223 C225 C226 C227 C228 C229: library part CMP-0006811-4, "CAP, CERM, 10 pF, 10 V, +/- 10%, X7R, 0603", Cap_Case=0603, Manufacturer=AVX, Supplier Part Number 1=0603ZC100KAT2A-ND, TempCo=X7R, Tolerance_%=10%, Value1=Unknown, Value2=10V, ValueDisplayed=10pF
C224 C231 C233 C406 C411: "CAP, CERM, 0.1 uF, 6.3 V, +/- 10%, X7R, 0402", Cap_Case=0402, Manufacturer=MuRata, PartNumber=GRM155R70J104KA01D, Supplier Part Number 1=GRM155R70J104KA01D-ND, TempCo=X7R, Tolerance_%=10%, Value1=Unknown, Value2=6.3V, ValueDisplayed=0.1uF
C230 C232 C234 C400 C401 C402 C421 C422 C423 C424: library part CMP-0115312-1, "WCAP-CSGP Multilayer Ceramic Chip Capacitor, General Purpose, size 0402, X7R, 100pF, 10VDC", Capacitance Tolerance=+/-10%, Case/Size Code=0402, Insulation Resistance=10GOhm, Manufacturer="Wurth Elektronik", Operating Temperature Max=125°C, Operating Temperature Min=-55°C, Rated Voltage (DC)=10V
C300 C301 C302: library part CMP-0011370-2, "CAP, AL, 100 uF, 63 V, +/- 20%, 0.19 ohm, SMD", Cap_Case=KE0, Manufacturer=Chemi-Con, Tolerance_%=20%, Value1="0.19 ohm", Value2=63V, ValueDisplayed=100uF
C306: library part EEE-FK1H220P, "CAP ALUM POLY HYB 22UF 63V SMD", Cap_Case=D, Manufacturer=Rubycon, Tolerance_%=20, Value1="0.88 ohm", Value2=63V, ValueDisplayed=22µF
C307: library part C3216X6S1H475K160AB, "CAP CER 4.7UF 100V X7S 1206", Cap_Case=1206, TempCo=X7S, Tolerance_%=10, Value2=100V, ValueDisplayed=4.7µF
C403: library part CMP-0097294-1, "0.1 µF ±10% 100V Ceramic Capacitor X7R 0603 (1608 Metric)", Digikey Part Number=732-885012206120TR-ND, Manufacturer="Wurth Electronics", Mouser Part Number=710-885012206120, Operating Temperature Range="-55°C to +125°C", TempCo=15%, Temperature Characteristic=X7R, Tolerance_%=10%, ValueDisplayed=100nF
C404: library part CMP-0861070-2, "CAP, CERM, 1 µF, 100 V,+/- 10%, X7R, AEC-Q200 Grade 1, 0805", Cap_Case=0805, Manufacturer=AVX, TempCo=X7R, Tolerance_%=10%, Value2=100V, ValueDisplayed=1µF
C405: library part CMP-0007404-5, "CAP, CERM, 0.1 uF, 25 V, +/- 10%, X7R, 0603", Cap_Case=0603, Manufacturer=MuRata, Supplier Part Number 1=490-1524-1-ND, TempCo=X7R, Tolerance_%=10%, Value1=Unknown, Value2=25V, ValueDisplayed=0.1uF
C407 C408 C409 C410 C412 C413 C414 C415 C416 C417 C418 C419 C420: library part CMP-0086419-2, "Cap Ceramic 0.015uF 50V X7R 10% Pad SMD 0603 125°C T/R", Manufacturer=Kemet, TempCo=15%, Tolerance_%=10%
C425 C426: library part CMP-0006982-4, "CAP, CERM, 220 pF, 50 V, +/- 10%, X7R, 0603", Cap_Case=0603, Manufacturer=Kemet, Supplier Part Number 1=399-5342-1-ND, TempCo=X7R, Tolerance_%=10%, Value1=Unknown, Value2=50V, ValueDisplayed=220pF
D200: library part CMP-0029006-2, "Diode, Ultrafast, 100 V, 0.25 A, SOD-323", Manufacturer=Nexperia, Value1=0.25A, Value2=1.4V
D201: library part CMP-0076927-2, "Diode, Switching, 100 V, 0.2 A, SOT-363", Manufacturer=Nexperia, Value1=0.2A, Value2=1.25V
D400: library part CMP-0028394-2, "Diode, Schottky, 80 V, 1 A, SMB", Manufacturer="Diodes Inc.", Value1=1A, Value2=0.79V
F300 F301 F302 F303 F304 F305: library part CMP-0003593-3, "Fuse, Resettable, 100 A, 24 VDC, SMD", Irating_A=100A, Manufacturer=Littelfuse, Supplier Part Number 1=MINIASMDC050F-2CT-ND
J200 J201: library part CMP-0081506-1, "FPC Connector, 1mm, 4 Pos, R/A, Tin, SMT", Color=Ivory, Current_A=800mA, Manufacturer="Wurth Elektronik", Supplier Part Number 1=732-11326-1-ND, Voltage_V=50V
J202: library part CMP-0003814-2, "C2000 controlCARD-120HSEC connector, SMT", Manufacturer=Samtec
J203: library part CMP-0003859-2, "C2000 controlCARD-180HSEC (60-pin addon) connector, SMT", Manufacturer=Samtec
J400: library part CMP-0082591-1, "FPC Connector, 0.5mm, 10 Pos, R/A, SMT", Current_A=500mA, Manufacturer=Molex, Supplier Part Number 1=WM12366CT-ND, Voltage_V=50V
Q200 Q207 Q209 Q210 Q211 Q400 Q401 Q402: library part CMP-0043768-1, "N-Channel 60 V 260mA (Ta) 200mW Surface Mount DFN1006-3", Digikey Part Number=353-2N7002KL3A-TPCT-ND, Drain To Source Breakdown Voltage=60V, Input Capacitace At Vds="21pF @ 30V", Manufacturer=MCC, Mouser Part Number=833-2N7002KL3A-TP, Operating Temperature Range="-55°C to +150°C", Power_W=0.2W, Pulse Drain Current=1.3A, Typ Forward Diode Voltage=0.9V
Q201 Q202 Q203 Q204: library part CMP-0000319-2, "Transistor, PNP, 45 V, 0.1 A, SOT-23", Manufacturer="Infineon Technologies", Supplier Part Number 1=BCX71KE6327INCT-ND, Value1="0.1 A", Value2=630
Q205: library part CMP-0000327-2, "Transistor, PNP, 40 V, 0.6 A, SOT-23", Manufacturer="Fairchild Semiconductor", Supplier Part Number 1=MMBT4403FSCT-ND, Value1="0.6 A", Value2=500
Q206 Q208: library part CMP-0000511-2, "Transistor, NPN, 50 V, 0.1 A, AEC-Q101, SOT-23", Manufacturer="ON Semiconductor", Supplier Part Number 1=MMUN2214LT1GOSCT-ND, Value1="0.1 A"
Q403: library part CMP-0122332-1, "N-Channel 80 V 31A (Ta), 323A (Tc) 3W (Ta), 333W (Tc) Surface Mount PG-TTFN-9-U02", Digikey Part Number=448-IQD016N08NM5CGATMA1CT-ND, Drain To Source Breakdown Voltage=80V, Input Capacitace At Vds="7100pF @ 40V", Manufacturer=Infineon, Mouser Part Number=726-IQD016N08NM5CGAT, Operating Temperature Range="-55°C to +175°C", Power_W=3W, Pulse Drain Current=1292A, Typ Forward Diode Voltage=0.82V
R200: library part CMP-0026466-2, "RES, 5.49 k, 1%, 0.063 W, AEC-Q200 Grade 0, 0402", Manufacturer=Vishay-Dale, Power_W=63mW, Supplier Part Number 1=541-5.49KLCT-ND, TempCo="100 ppm/C", Tolerance_%=1%, Value2=0.063W, Value_Code=5k49, ValueDisplayed=5.49k
R201: library part CMP-0026027-3, "RES, 15.0 k, 1%, 0.063 W, AEC-Q200 Grade 0, 0402", Manufacturer=Vishay-Dale, Power_W=63mW, Supplier Part Number 1=541-15.0KLCT-ND, TempCo="100 ppm/C", Tolerance_%=1%, Value2=0.063W, Value_Code=15k0, ValueDisplayed=15.0k
R202 R459: library part CMP-0026717-1, "RES, 10.0, 1%, 0.063 W, 0402", Manufacturer=Rohm, Power_W=63mW, Supplier Part Number 1=RHM10.0LCT-ND, TempCo="100 ppm/C", Tolerance_%=1%, Value2=0.063W, Value_Code=10R0, ValueDisplayed=10.0
R203 R205 R210 R212 R237: "RES, 0, 5%, 0.1 W, 0603", Manufacturer="Yageo America", Power_W=0.1, Supplier Part Number 1=311-0.0GRCT-ND, TempCo="200 ppm/C", Tolerance_%=5, Value1=5%, Value2=0.1W, Value_Code=0000, ValueDisplayed=0
R204 R206 R211 R213: "RES, 100, 1%, 0.1 W, 0603", Manufacturer="Yageo America", Power_W=0.1, Supplier Part Number 1=311-100HRCT-ND, TempCo="200 ppm/C", Tolerance_%=1, Value1=1%, Value2=0.1W, Value_Code=100R, ValueDisplayed=100
R207 R214 R239 R245 R246 R247 R409 R410 R418 R419 R420 R421 R423 R424 R430 R431 R432 R439 R443 R444 R445 R452 R456 R457 R458: library part CMP-0120043-1, "10 kOhms ±1% 0.1W, 1/10W Chip Resistor 0402 (1005 Metric) Anti-Sulfur, Automotive AEC-Q200 Thick Film", Digikey Part Number=10-ERJ-U02F1002XCT-ND, Manufacturer=Panasonic, Mouser Part Number=667-ERJ-U02F1002X, Operating Temperature Range="-55°C to +155°C", Power_W=100mW, TempCo=200ppm/°C, Tolerance_%=1%
R208 R216: library part CMP-0026329-2, "RES, 3.01 k, 1%, 0.063 W, AEC-Q200 Grade 0, 0402", Manufacturer=Vishay-Dale, Power_W=63mW, Supplier Part Number 1=541-3.01KLCT-ND, TempCo="100 ppm/C", Tolerance_%=1%, Value2=0.063W, Value_Code=3k01, ValueDisplayed=3.01k
R209: library part CMP-0023162-4, "RES, 510 k, 1%, 0.1 W, 0603", Manufacturer=Yageo, Power_W=100mW, Supplier Part Number 1=311-510KHRCT-ND, TempCo="100 ppm/C", Tolerance_%=1%, Value2=0.1W, Value_Code=510k
R215: library part CMP-0026336-2, "RES, 3.57 k, 1%, 0.063 W, AEC-Q200 Grade 0, 0402", Manufacturer=Vishay-Dale, Power_W=63mW, Supplier Part Number 1=541-3.57KLCT-ND, TempCo="100 ppm/C", Tolerance_%=1%, Value2=0.063W, Value_Code=3k57, ValueDisplayed=3.57k
R217: library part CMP-0026668-1, "RES, 1.50 k, 1%, 0.1 W, AEC-Q200 Grade 0, 0402", Manufacturer=Panasonic, Power_W=100mW, Supplier Part Number 1=P1.50KLCT-ND, TempCo="100 ppm/C", Tolerance_%=1%, Value2=0.1W, Value_Code=1k50, ValueDisplayed=1.50k
R218 R223 R231 R234: library part CMP-0026906-3, "RES, 330, 5%, 0.063 W, AEC-Q200 Grade 0, 0402", Manufacturer=Vishay-Dale, Power_W=63mW, Supplier Part Number 1=541-330JCT-ND, TempCo="200 ppm/C", Tolerance_%=5%, Value2=0.063W, Value_Code=330R, ValueDisplayed=330
R219 R230: library part CMP-0089152-1, "100 Ohms ±1% 0.125W, 1/8W Chip Resistor 0603 (1608 Metric) Automotive AEC-Q200, Moisture Resistant Thick Film", Approved Alternate Part Number=541-1.00HHCT-ND, Digikey Part Number=2019-RK73H1JTTD1000FCT-ND, Manufacturer="KOA Speer", Mouser Part Number=660-RK73H1JTTD1000F, Operating Temperature Range="-55°C to +155°C", Power=100mW, TempCo=100ppm/°C, Tolerance_%=1%, Voltage=75V
R220 R222 R224 R225: "RES, 28.7 k, 1%, 0.1 W, 0603", Manufacturer=Vishay-Dale, Power_W=0.1, Supplier Part Number 1=541-28.7KHCT-ND, TempCo="100 ppm/C", Tolerance_%=1, Value1=1%, Value2=0.1W, Value_Code=28k7, ValueDisplayed=28.7k
R221 R226: library part CMP-0022973-5, "RES, 28.7 k, 1%, 0.1 W, 0603", Manufacturer=Yageo, Power_W=100mW, Supplier Part Number 1=311-28.7KHRCT-ND, TempCo="100 ppm/C", Tolerance_%=1%, Value2=0.1W, Value_Code=28k7, ValueDisplayed=28.7k
R227: "RES, 3.01 k, 1%, 0.1 W, 0603", Manufacturer=Vishay-Dale, Power_W=0.1, Supplier Part Number 1=541-3.01KHCT-ND, TempCo="100 ppm/C", Tolerance_%=1, Value1=1%, Value2=0.1W, Value_Code=3k01, ValueDisplayed=3.01k
R228 R229: library part CMP-0024186-3, "RES, 3.01 k, 0.1%, 0.1 W, 0603", Manufacturer="Yageo America", Power_W=100mW, TempCo="25 ppm/C", Tolerance_%=0.1%, Value2=0.1W, Value_Code=3k01, ValueDisplayed=3.01k
R232 R233 R270 R271 R306 R307: library part CMP-0120804-1, "Resistor Thick Film 0603 Jumper 0 Ohm ±5% 1/10W Molded Paper T/R", Digikey Part Number=13-RC0603JR-130RPCT-ND, Manufacturer=Yageo, Operating Temperature Range="-55°C to +155°C", Power_W=100mW
R235: library part CMP-0094956-1, "0 Ohms Jumper 0.1W, 1/10W Chip Resistor 0603 (1608 Metric) - Thick Film", Digikey Part Number=2679-CR0603-10W-000TTR-ND, Manufacturer=Venkel, Operating Temperature Range="-55°C to +155°C", Power_W=100mW
R236 R241 R248: library part CMP-0026229-2, "RES, 2.10 k, 1%, 0.063 W, AEC-Q200 Grade 0, 0402", Manufacturer=Vishay-Dale, Power_W=63mW, Supplier Part Number 1=541-2.10KLCT-ND, TempCo="100 ppm/C", Tolerance_%=1%, Value2=0.063W, Value_Code=2k10, ValueDisplayed=2.10k
R238 R240 R242: library part CMP-0124663-1, "0 Ohms Jumper 0.05W, 1/20W Chip Resistor 0201 (0603 Metric) Thick Film", Digikey Part Number=3372-CR0201PM0RS001TR-ND, Manufacturer="NextGen Components", Operating Temperature Range="-55°C to +125°C", Power_W=50mW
